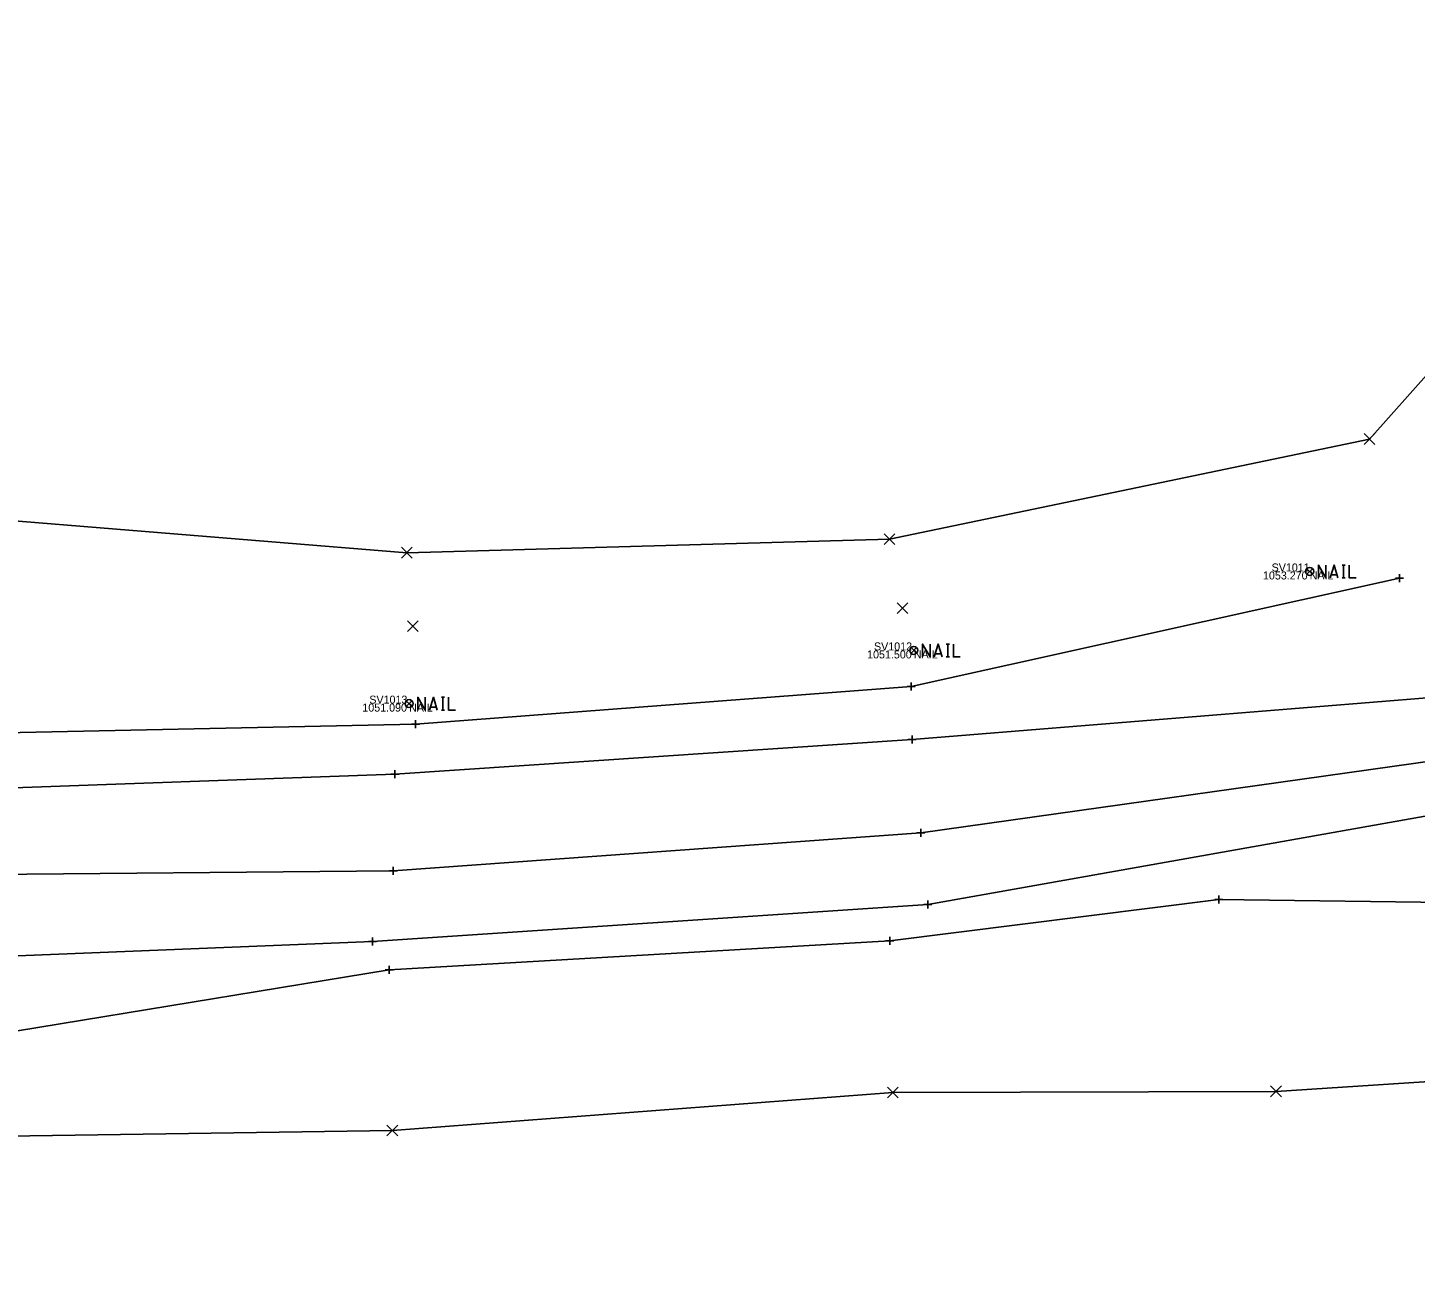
# Model space of a CAD drawing. Extents: x 1620404 to 1621386, y 607070 to 607748.
# Drawn here: x 1620582.5 to 1620755.9, y 607208 to 607362.2 of the extents above; entities that cross this region are included whole.
import ezdxf

# ---------------------------------------------------------------- set-up
doc = ezdxf.new("R2010")
doc.units = 0
for name, color, linetype in [('BD_X_Building', 7, 'Continuous'), ('Default', 7, 'Continuous'), ('DR_X_Elev_Flow', 7, 'Continuous'), ('PV_X_Curb', 7, 'Continuous'), ('SN_X_Public', 7, 'Continuous'), ('SV_P_Control_Cells_Set', 7, 'Continuous'), ('SV_X_Shot_Marker', 7, 'Continuous'), ('UT_X_Gas_Cells', 7, 'Continuous'), ('UT_X_Sanitary_Cells', 7, 'Continuous'), ('UT_X_Water', 7, 'Continuous')]:
    doc.layers.add(name, color=color, linetype=linetype)

msp = doc.modelspace()

# ---------------------------------------------------------------- linework, layer by layer
at = {"layer": 'Default'}
for points in [[(1620938.47, 607671.36), (1620937.81, 607643.56), (1620937.14, 607610.92), (1620935.32, 607584.43), (1620928.86, 607551.19), (1620925.2, 607530.23), (1620871.8, 607449.09), (1620881.05, 607424.84), (1620891.59, 607408.35), (1620892.98, 607397.59), (1620883.1, 607388.07), (1620854.92, 607372.94), (1620830.83, 607363.59), (1620765.8, 607328.27), (1620750.23, 607310.78), (1620690.21, 607298.27), (1620629.9, 607296.57), (1620577.73, 607300.81), (1620516.58, 607288.7), (1620453.85, 607273.55), (1620404.49, 607262.35)], [(1620404.49, 607262.35), (1620405.83, 607252.96), (1620406.05, 607243.78), (1620405.74, 607236.29), (1620407.09, 607227.35), (1620411.31, 607219.96), (1620412.34, 607207.99), (1620462.23, 607211.46), (1620515.82, 607221.18), (1620574.22, 607223.55), (1620628.08, 607224.35), (1620690.63, 607229.09), (1620738.53, 607229.23), (1620765.36, 607230.97)]]:
    msp.add_lwpolyline(points, dxfattribs=at)
at = {"layer": 'DR_X_Elev_Flow'}
for p, q in [((1620742.39, 607294.57), (1620743.09, 607293.87)), ((1620742.39, 607293.87), (1620743.09, 607294.57)), ((1620692.91, 607284.7), (1620693.61, 607284)), ((1620692.91, 607284), (1620693.61, 607284.7)), ((1620629.82, 607278.05), (1620630.52, 607277.35)), ((1620629.82, 607277.35), (1620630.52, 607278.05))]:
    msp.add_line(p, q, dxfattribs=at)
for points in [[(1620743.83, 607293.41), (1620743.83, 607295.01), (1620744.77, 607293.41), (1620744.77, 607295.01)], [(1620745.28, 607293.41), (1620745.78, 607295.01), (1620746.27, 607293.41)], [(1620746.15, 607293.79), (1620745.4, 607293.79)], [(1620746.78, 607295.01), (1620747.18, 607295.01)], [(1620746.98, 607293.41), (1620746.98, 607295.01)], [(1620747.68, 607295.01), (1620747.68, 607293.41), (1620748.55, 607293.41)], [(1620746.78, 607293.41), (1620747.18, 607293.41)], [(1620694.35, 607283.54), (1620694.35, 607285.14), (1620695.29, 607283.54), (1620695.29, 607285.14)], [(1620695.8, 607283.54), (1620696.3, 607285.14), (1620696.79, 607283.54)], [(1620697.3, 607285.14), (1620697.7, 607285.14)], [(1620697.5, 607283.54), (1620697.5, 607285.14)], [(1620698.2, 607285.14), (1620698.2, 607283.54), (1620699.07, 607283.54)], [(1620696.67, 607283.92), (1620695.92, 607283.92)], [(1620697.3, 607283.54), (1620697.7, 607283.54)], [(1620631.26, 607276.89), (1620631.26, 607278.49), (1620632.2, 607276.89), (1620632.2, 607278.49)], [(1620632.71, 607276.89), (1620633.21, 607278.49), (1620633.7, 607276.89)], [(1620634.21, 607278.49), (1620634.61, 607278.49)], [(1620634.41, 607276.89), (1620634.41, 607278.49)], [(1620635.11, 607278.49), (1620635.11, 607276.89), (1620635.98, 607276.89)], [(1620633.58, 607277.27), (1620632.83, 607277.27)], [(1620634.21, 607276.89), (1620634.61, 607276.89)]]:
    msp.add_lwpolyline(points, dxfattribs=at)
for centre in [(1620742.74, 607294.22), (1620693.26, 607284.35), (1620630.17, 607277.7)]:
    msp.add_circle(centre, 0.5, dxfattribs=at)
at = {"layer": 'PV_X_Curb'}
msp.add_lwpolyline([(1620758.66, 607270.63), (1620694.14, 607261.55), (1620628.2, 607256.8), (1620573.18, 607256.29), (1620522.11, 607249.56), (1620461.71, 607244.54), (1620405.74, 607236.29)], dxfattribs=at)
at = {"layer": 'SN_X_Public'}
for p, q in [((1620753.96, 607293.88), (1620753.96, 607292.88)), ((1620753.46, 607293.38), (1620754.46, 607293.38)), ((1620753.96, 607293.38), (1620753.96, 607293.38)), ((1620692.42, 607279.83), (1620693.42, 607279.83)), ((1620692.92, 607280.33), (1620692.92, 607279.33)), ((1620692.92, 607279.83), (1620692.92, 607279.83)), ((1620630.49, 607275.15), (1620631.49, 607275.15)), ((1620630.99, 607275.65), (1620630.99, 607274.65)), ((1620630.99, 607275.15), (1620630.99, 607275.15)), ((1620692.56, 607273.23), (1620693.56, 607273.23)), ((1620693.06, 607273.73), (1620693.06, 607272.73)), ((1620693.06, 607273.23), (1620693.06, 607273.23)), ((1620628.37, 607269.39), (1620628.37, 607268.39)), ((1620627.87, 607268.89), (1620628.87, 607268.89)), ((1620628.37, 607268.89), (1620628.37, 607268.89)), ((1620693.64, 607261.55), (1620694.64, 607261.55)), ((1620694.14, 607262.05), (1620694.14, 607261.05)), ((1620694.14, 607261.55), (1620694.14, 607261.55)), ((1620628.2, 607257.3), (1620628.2, 607256.3)), ((1620627.7, 607256.8), (1620628.7, 607256.8)), ((1620628.2, 607256.8), (1620628.2, 607256.8)), ((1620731.39, 607253.7), (1620731.39, 607252.7)), ((1620694.52, 607252.59), (1620695.52, 607252.59)), ((1620695.02, 607253.09), (1620695.02, 607252.09)), ((1620695.02, 607252.59), (1620695.02, 607252.59)), ((1620730.89, 607253.2), (1620731.89, 607253.2)), ((1620731.39, 607253.2), (1620731.39, 607253.2)), ((1620625.61, 607248.47), (1620625.61, 607247.47)), ((1620690.26, 607248.55), (1620690.26, 607247.55)), ((1620625.11, 607247.97), (1620626.11, 607247.97)), ((1620625.61, 607247.97), (1620625.61, 607247.97)), ((1620689.76, 607248.05), (1620690.76, 607248.05)), ((1620690.26, 607248.05), (1620690.26, 607248.05)), ((1620627.19, 607244.43), (1620628.19, 607244.43)), ((1620627.69, 607244.93), (1620627.69, 607243.93)), ((1620627.69, 607244.43), (1620627.69, 607244.43))]:
    msp.add_line(p, q, dxfattribs=at)
at = {"layer": 'SV_X_Shot_Marker'}
for p, q in [((1620749.56, 607310.11), (1620750.9, 607311.45)), ((1620749.56, 607311.45), (1620750.9, 607310.11)), ((1620689.54, 607297.6), (1620690.88, 607298.94)), ((1620689.54, 607298.94), (1620690.88, 607297.6)), ((1620629.23, 607295.9), (1620630.57, 607297.24)), ((1620629.23, 607297.24), (1620630.57, 607295.9)), ((1620691.17, 607288.97), (1620692.51, 607290.31)), ((1620691.17, 607290.31), (1620692.51, 607288.97)), ((1620629.97, 607286.72), (1620631.31, 607288.06)), ((1620629.97, 607288.06), (1620631.31, 607286.72)), ((1620689.96, 607228.42), (1620691.3, 607229.76)), ((1620689.96, 607229.76), (1620691.3, 607228.42)), ((1620737.86, 607228.56), (1620739.2, 607229.9)), ((1620737.86, 607229.9), (1620739.2, 607228.56)), ((1620627.41, 607223.68), (1620628.75, 607225.02)), ((1620627.41, 607225.02), (1620628.75, 607223.68))]:
    msp.add_line(p, q, dxfattribs=at)
at = {"layer": 'UT_X_Gas_Cells'}
for points in [[(1620753.96, 607293.38), (1620692.92, 607279.83), (1620630.99, 607275.15), (1620577.54, 607274.02), (1620520.82, 607267.73)], [(1620411.31, 607219.96), (1620462.7, 607227.75), (1620517.29, 607232.73), (1620572.79, 607235.42), (1620627.69, 607244.43), (1620690.26, 607248.05), (1620731.39, 607253.2), (1620759.79, 607252.84)]]:
    msp.add_lwpolyline(points, dxfattribs=at)
at = {"layer": 'UT_X_Sanitary_Cells'}
for points in [[(1620757.91, 607278.47), (1620693.06, 607273.23), (1620628.37, 607268.89), (1620574.91, 607266.98), (1620520.44, 607260.44), (1620461.07, 607252.77), (1620406.05, 607243.78)], [(1620759.07, 607263.96), (1620695.02, 607252.59), (1620625.61, 607247.97), (1620572.94, 607245.84), (1620521.46, 607239.48), (1620462.29, 607234.97), (1620407.09, 607227.35)]]:
    msp.add_lwpolyline(points, dxfattribs=at)

# ---------------------------------------------------------------- texts
at = {"layer": 'BD_X_Building'}
for p in [(1620742.74, 607293.22), (1620693.26, 607283.35), (1620630.17, 607276.7)]:
    msp.add_text('NAIL', height=1, dxfattribs=at).set_placement(p)
at = {"layer": 'SV_P_Control_Cells_Set'}
for s, p in [('SV1011', (1620737.98, 607294.22)), ('SV1012', (1620688.28, 607284.35)), ('SV1013', (1620625.2, 607277.7))]:
    msp.add_text(s, height=1, dxfattribs=at).set_placement(p)
at = {"layer": 'UT_X_Water'}
for s, p in [('1053.270', (1620736.9, 607293.22)), ('1051.500', (1620687.42, 607283.35)), ('1051.090', (1620624.33, 607276.7))]:
    msp.add_text(s, height=1, dxfattribs=at).set_placement(p)

doc.saveas('drawing.dxf')
